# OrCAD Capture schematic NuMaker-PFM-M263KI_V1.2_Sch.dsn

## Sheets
1 Nu-Link2-Me: size A3; title: Nu-Link2-Me; rev: 1.0; company: CMHuang; note: Nu-Link2-Me
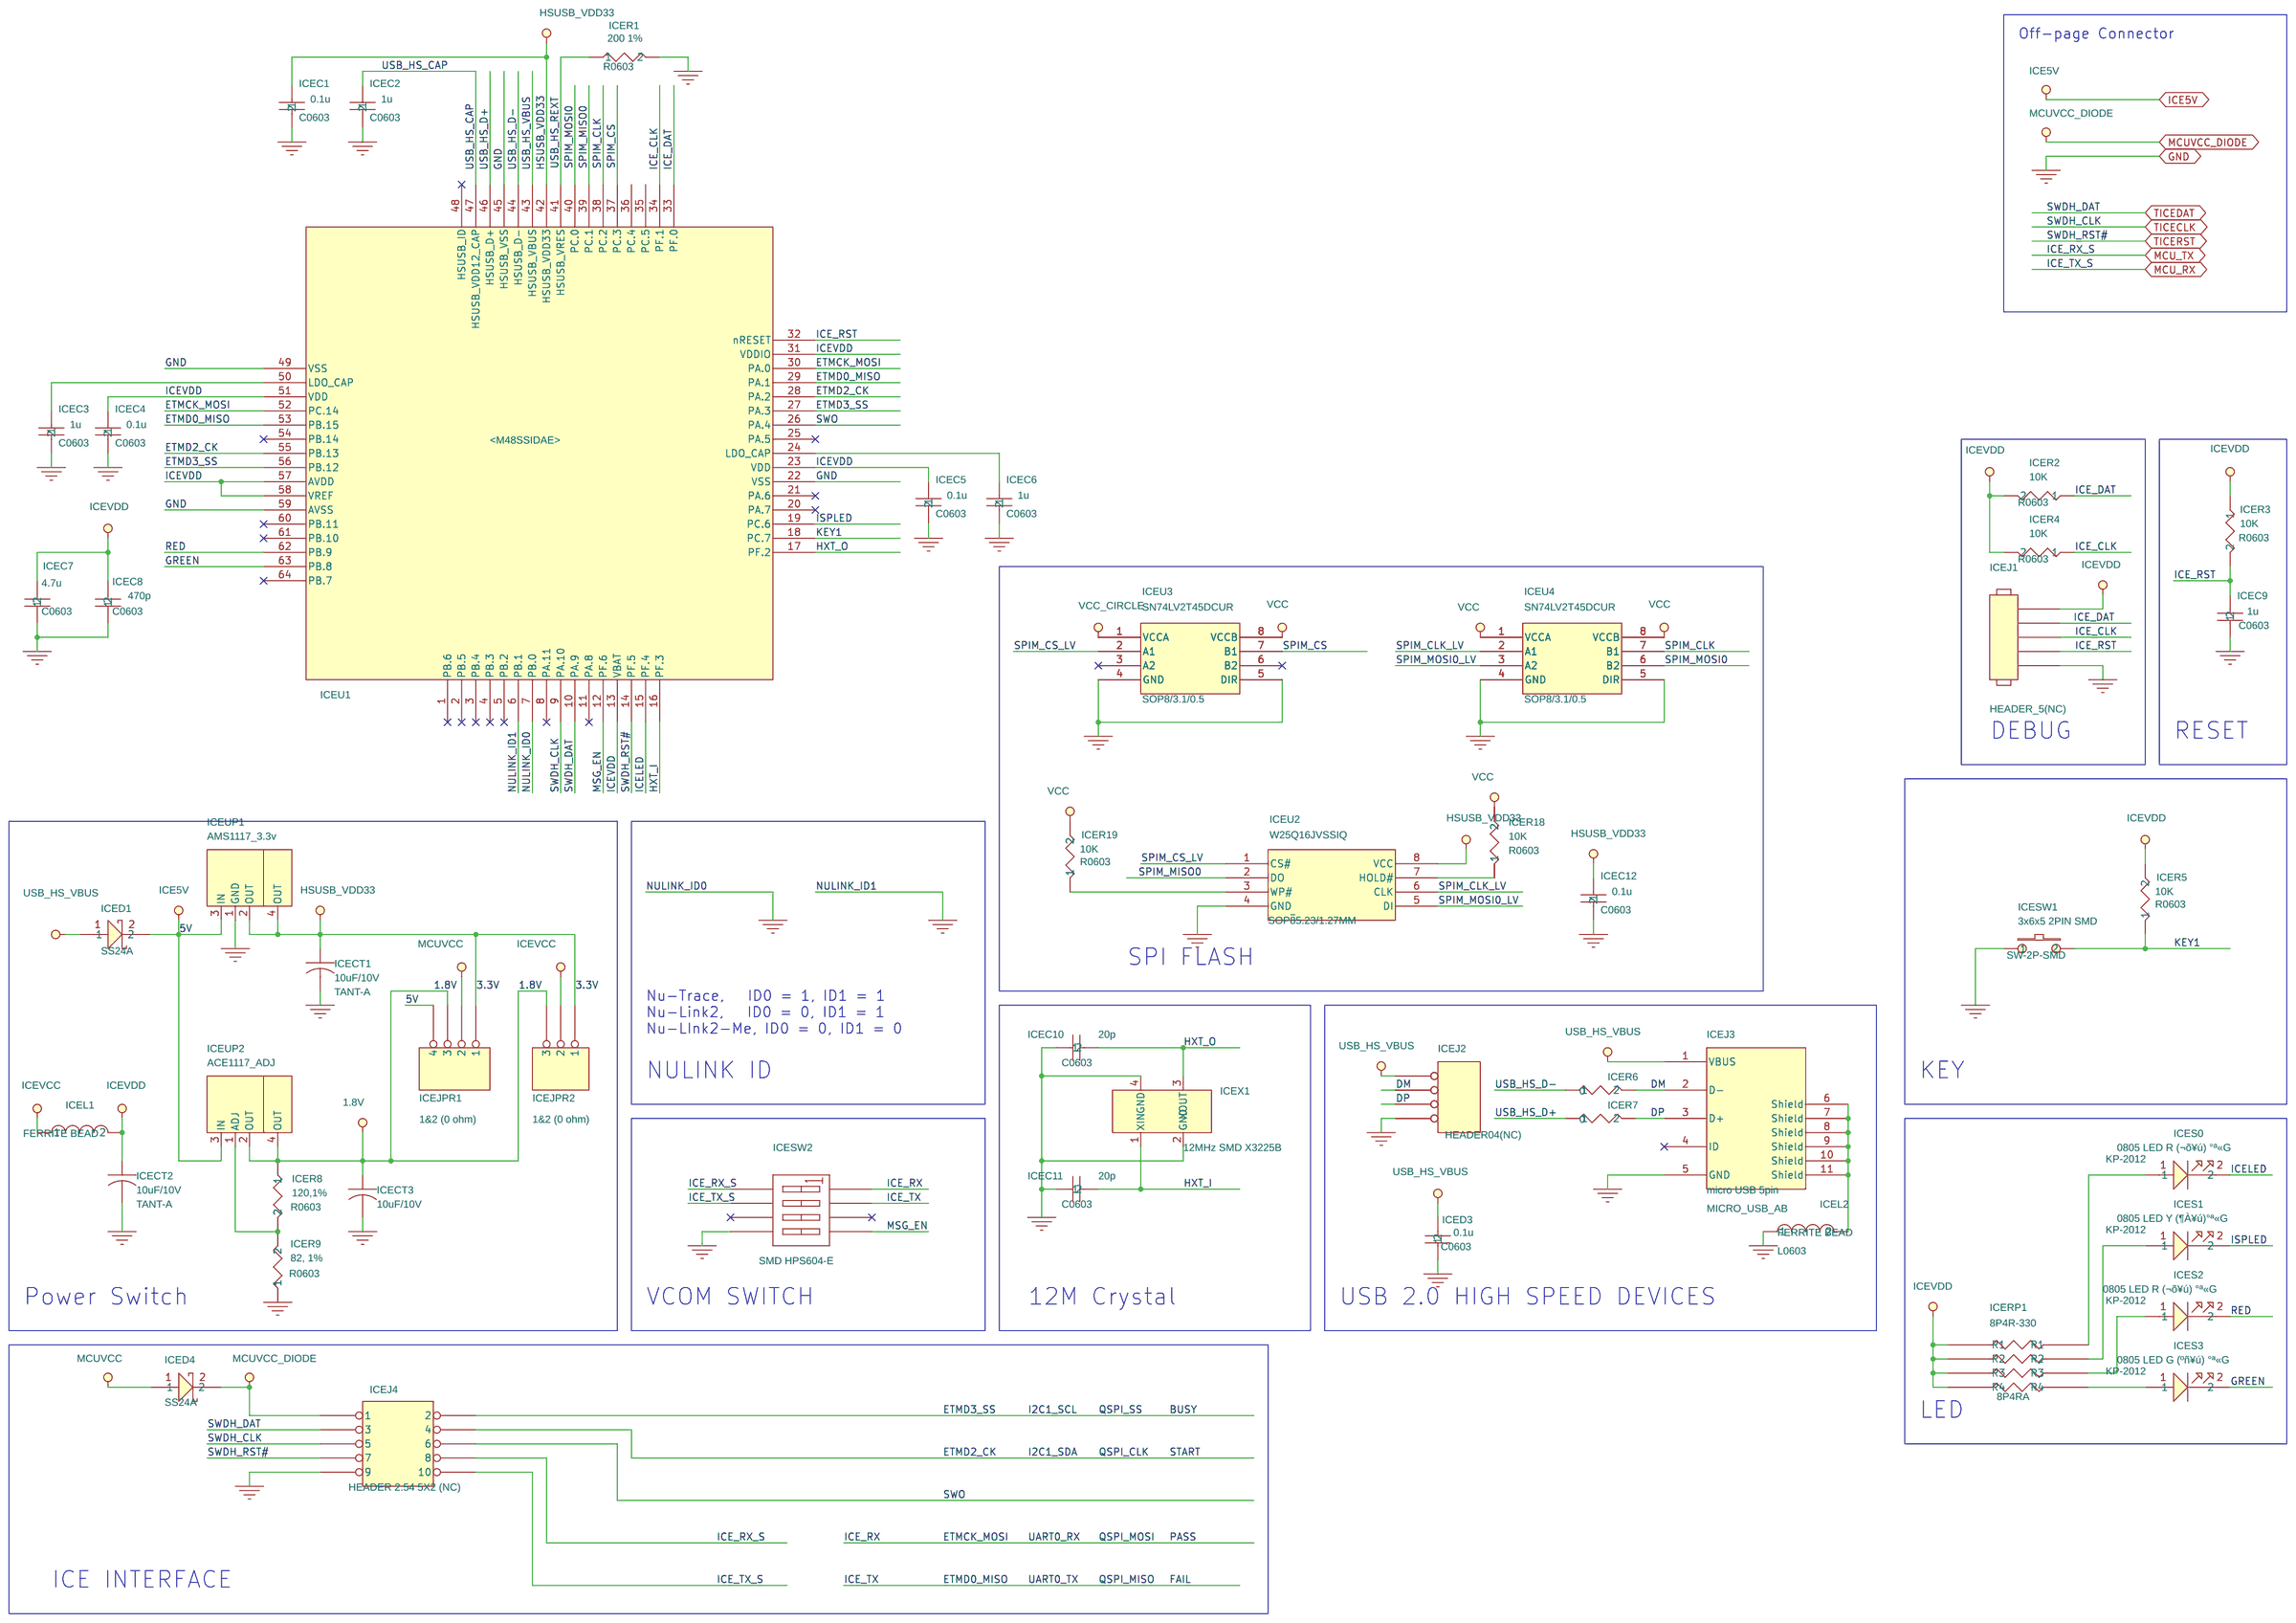
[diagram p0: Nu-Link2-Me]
2 M263KIAAE: size Custom; title: M263KIAAE; rev: v1.2; note: NuMaker-PFM-M263KI
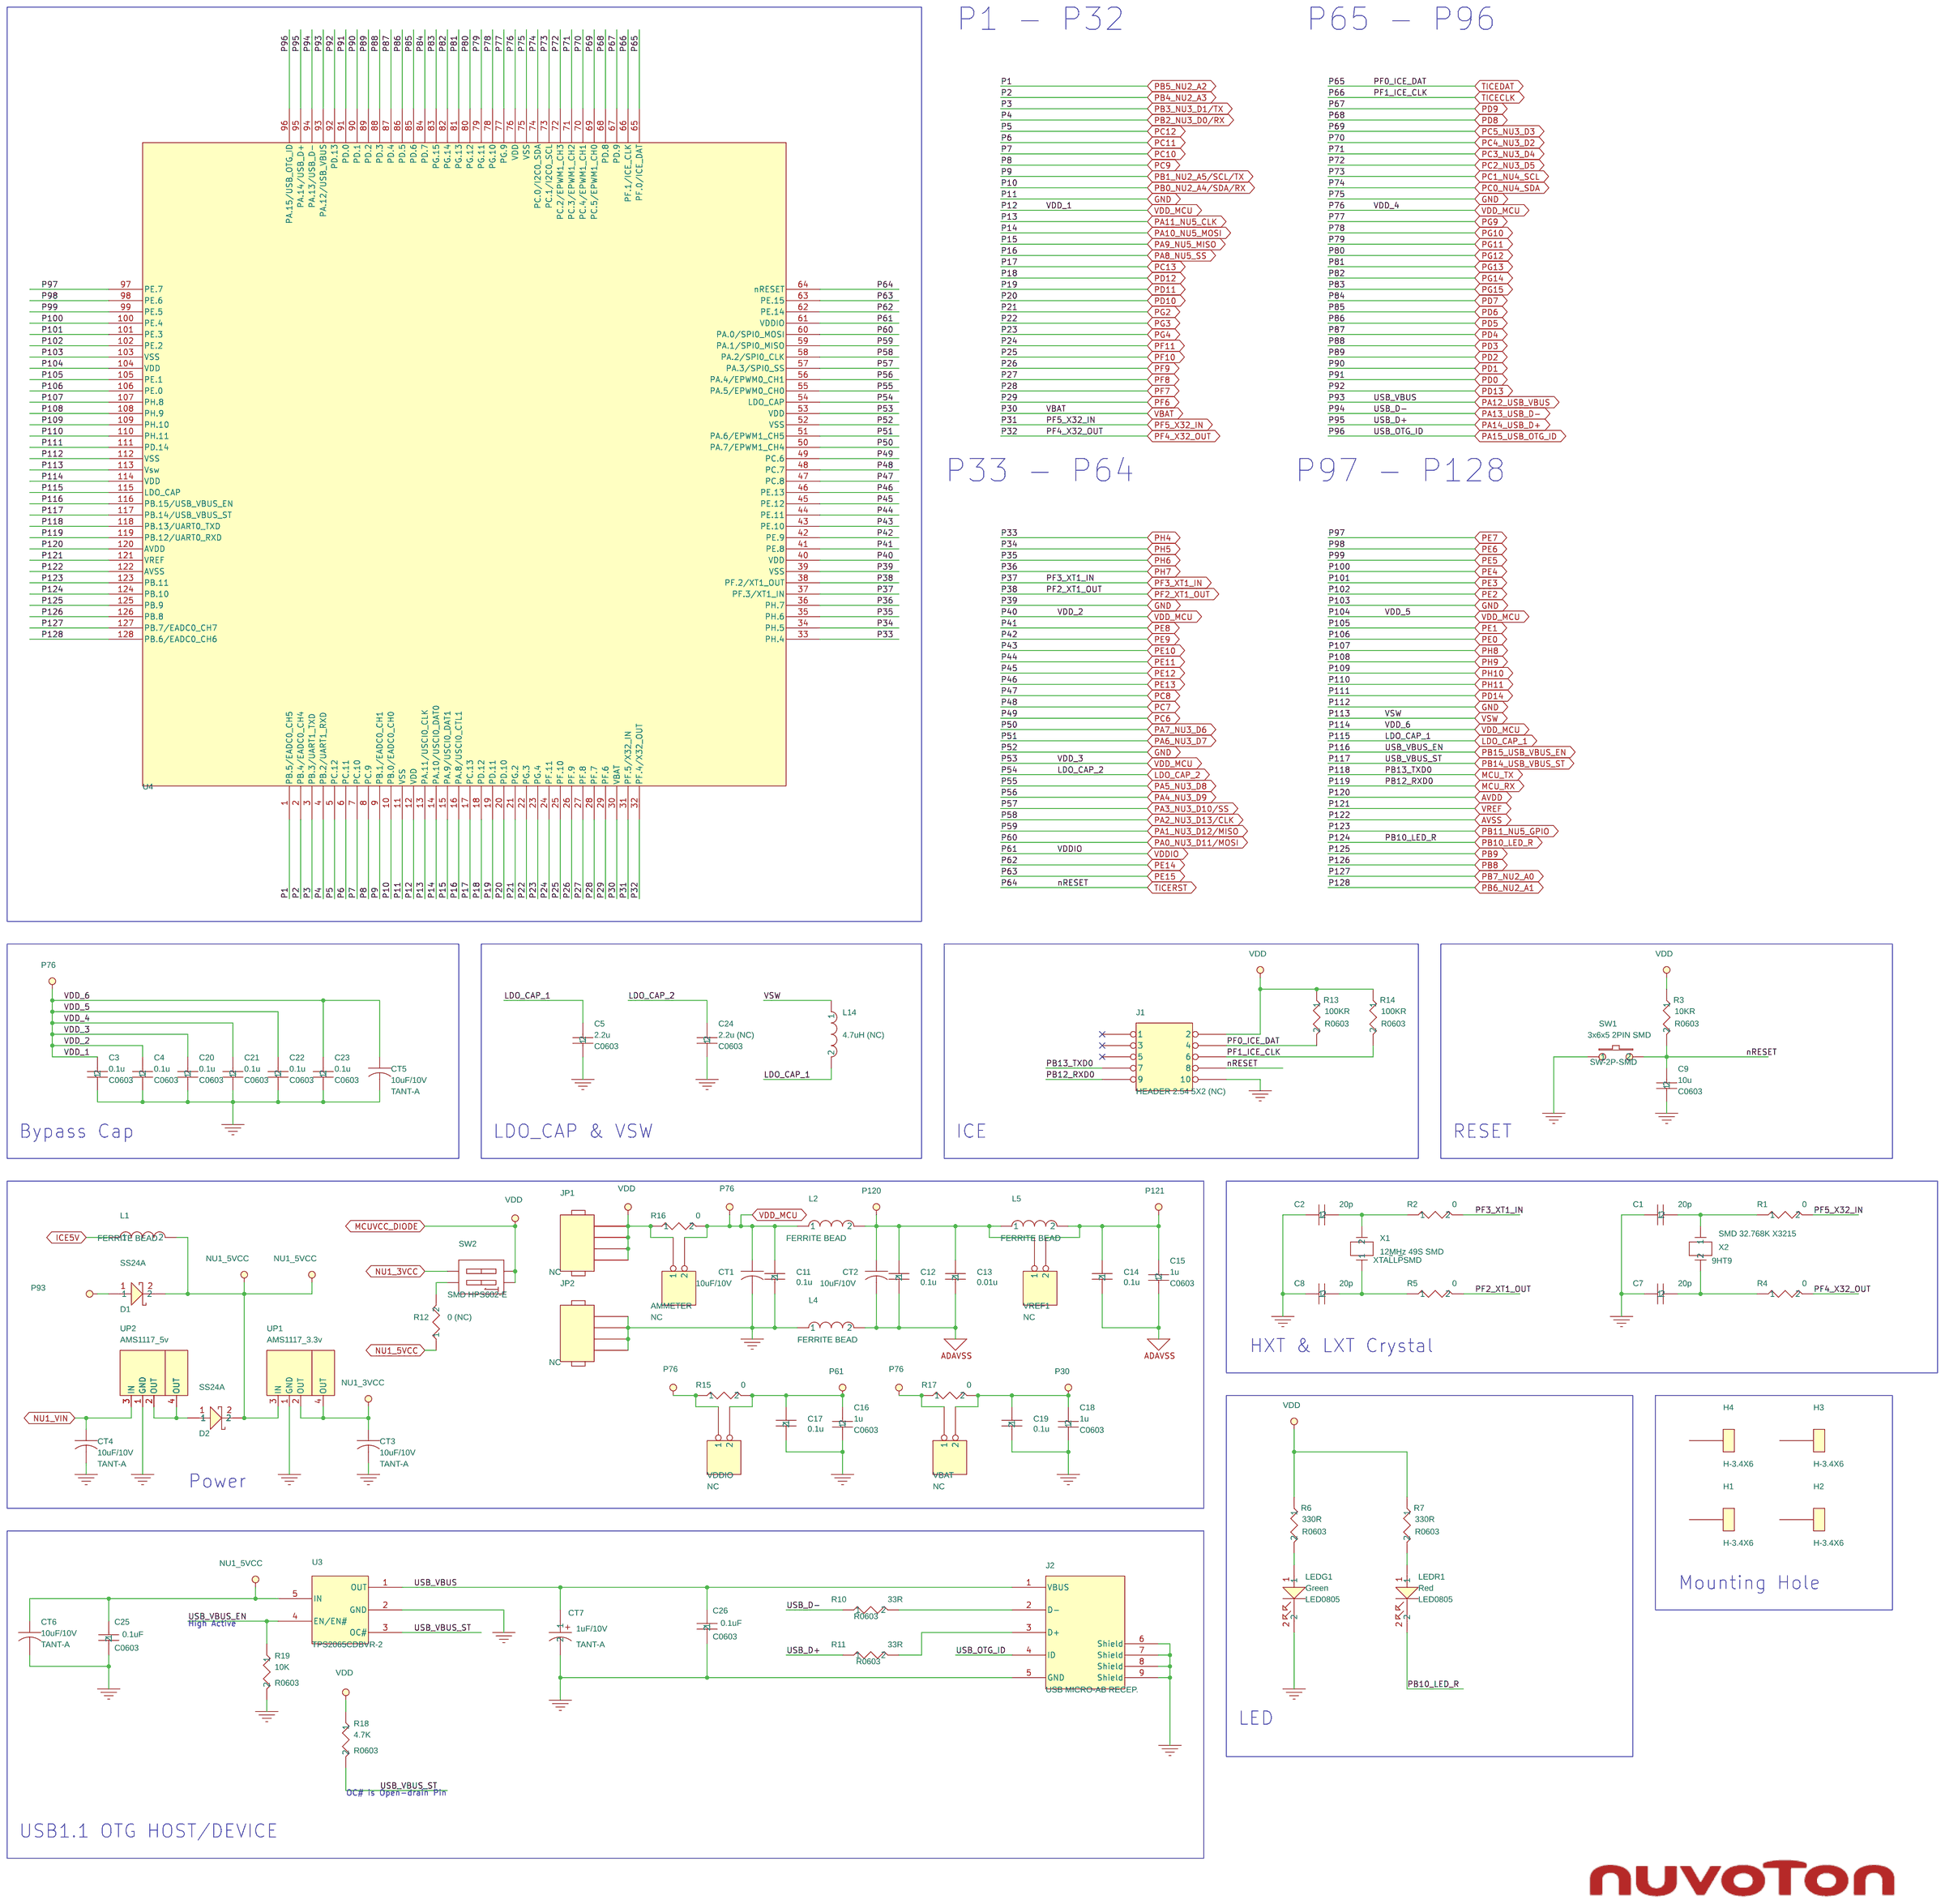
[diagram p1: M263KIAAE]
3 Ext. Connector: size Custom; title: Ext. Connector; rev: v1.2; note: NuMaker-PFM-M263KI
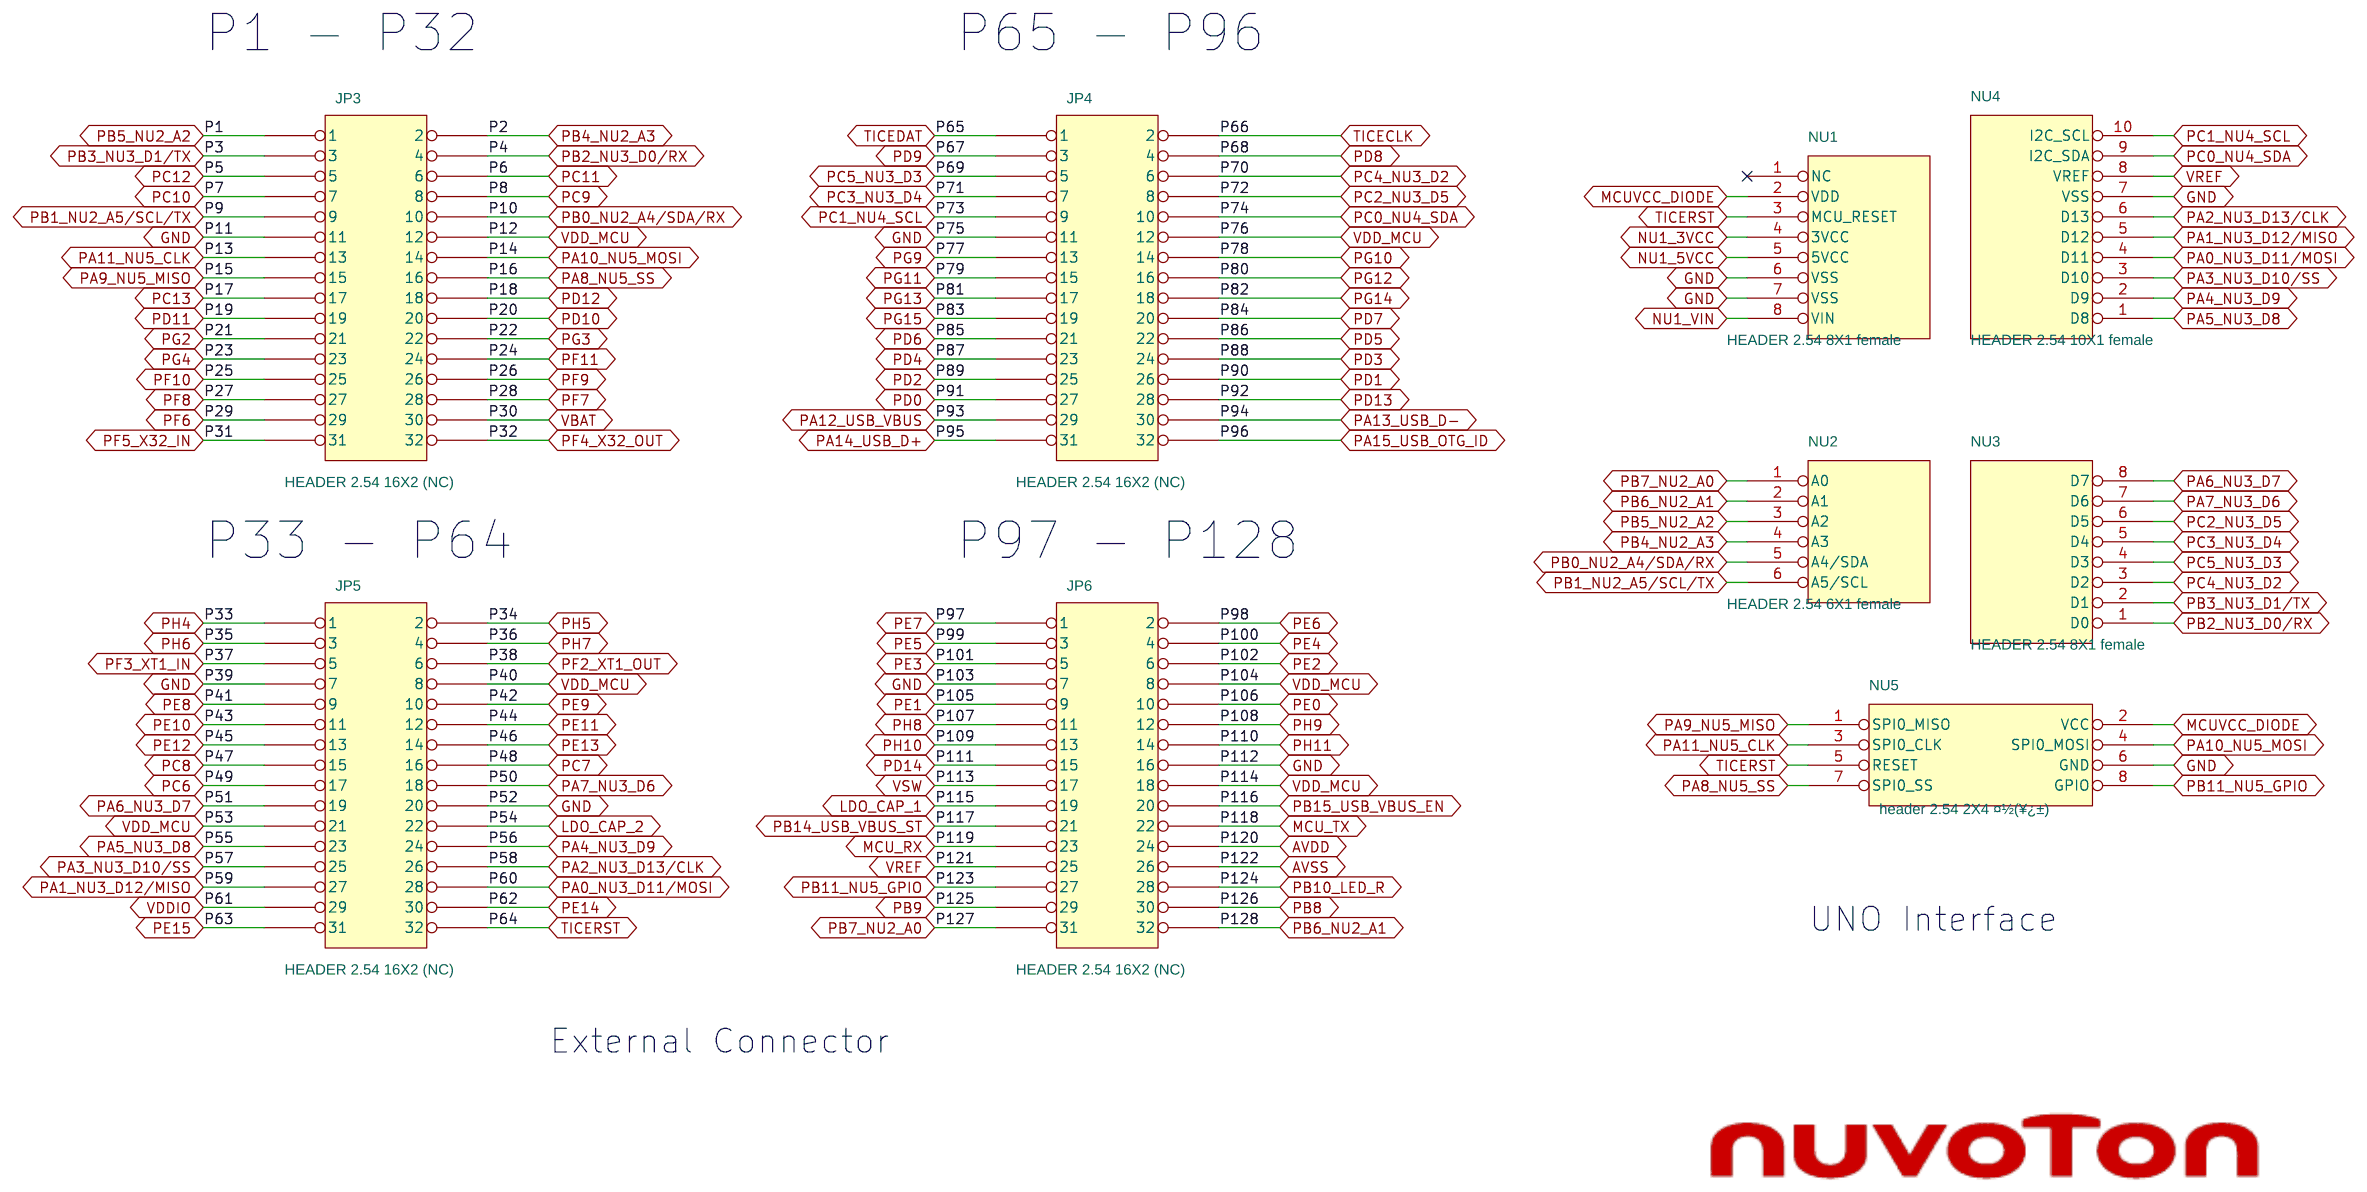
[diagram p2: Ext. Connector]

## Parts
sheet Ext. Connector
JP3  HEADER 2.54 16X2 (NC)  [HEADER16X2]
JP4  HEADER 2.54 16X2 (NC)  [HEADER16X2]
JP5  HEADER 2.54 16X2 (NC)  [HEADER16X2]
JP6  HEADER 2.54 16X2 (NC)  [HEADER16X2]
NU1  HEADER 2.54 8X1 female  [SIP-8P]
NU2  HEADER 2.54 6X1 female  [SIP-6P]
NU3  HEADER 2.54 8X1 female  [SIP-8P]
NU4  HEADER 2.54 10X1 female  [SIP-10P]
NU5  header 2.54 2X4 ¤½(¥¿­±)  [HEADER4X2]
sheet M263KIAAE
AMMETER  NC  [HEADER2X1]
C1  20p  [C0603]
C2  20p  [C0603]
C3  0.1u  [C0603]
C4  0.1u  [C0603]
C5  2.2u  [C0603]
C7  20p  [C0603]
C8  20p  [C0603]
C9  10u  [C0603]
C11  0.1u  [C0603]
C12  0.1u  [C0603]
C13  0.01u  [C0603]
C14  0.1u  [C0603]
C15  1u  [C0603]
C16  1u  [C0603]
C17  0.1u  [C0603]
C18  1u  [C0603]
C19  0.1u  [C0603]
C20  0.1u  [C0603]
C21  0.1u  [C0603]
C22  0.1u  [C0603]
C23  0.1u  [C0603]
C24  2.2u (NC)  [C0603]
C25  0.1uF  [C0603]
C26  0.1uF  [C0603]
CT1  10uF/10V  [TANT-A]
CT2  10uF/10V  [TANT-A]
CT3  10uF/10V  [TANT-A]
CT4  10uF/10V  [TANT-A]
CT5  10uF/10V  [TANT-A]
CT6  10uF/10V  [TANT-A]
CT7  1uF/10V  [TANT-A]
D1  SS24A  [RB060L]
D2  SS24A  [RB060L]
H1  H-3.4X6  [H-3.4X6]
H2  H-3.4X6  [H-3.4X6]
H3  H-3.4X6  [H-3.4X6]
H4  H-3.4X6  [H-3.4X6]
J1  HEADER 2.54 5X2 (NC)  [HEADER5X2]
J2  USB MICRO-AB RECEP.  [MICRO_USB_AB_LS]
JP1  NC  [header1x4]
JP2  NC  [header1x4]
L1  FERRITE BEAD  [L0603]
L2  FERRITE BEAD  [L0603]
L4  FERRITE BEAD  [L0603]
L5  FERRITE BEAD  [L0603]
L14  4.7uH (NC)  [L-VLF403215MT]
LEDG1  Green  [LED0805]
LEDR1  Red  [LED0805]
R1  0  [R0603]
R2  0  [R0603]
R3  10KR  [R0603]
R4  0  [R0603]
R5  0  [R0603]
R6  330R  [R0603]
R7  330R  [R0603]
R10  33R  [R0603]
R11  33R  [R0603]
R12  0 (NC)  [R0603]
R13  100KR  [R0603]
R14  100KR  [R0603]
R15  0  [R0603]
R16  0  [R0603]
R17  0  [R0603]
R18  4.7K  [R0603]
R19  10K  [R0603]
SW1  3x6x5 2PIN SMD  [SW-2P-SMD]
SW2  SMD HPS602-E  [SW1X2]
U3  TPS2065CDBVR-2  [SOT23-5]
U4  M263KIAAE  [MCU_LQFP_128_USB1_1]
UP1  AMS1117_3.3v  [SOT-223-1]
UP2  AMS1117_5v  [SOT-223-1]
VBAT  NC  [HEADER2X1]
VDDIO  NC  [HEADER2X1]
VREF1  NC  [HEADER2X1]
X1  12MHz 49S SMD  [XTAL\LP\SMD]
X2  SMD 32.768K X3215  [9HT9]
sheet Nu-Link2-Me
ICEC1  0.1u  [C0603]
ICEC2  1u  [C0603]
ICEC3  1u  [C0603]
ICEC4  0.1u  [C0603]
ICEC5  0.1u  [C0603]
ICEC6  1u  [C0603]
ICEC7  4.7u  [C0603]
ICEC8  470p  [C0603]
ICEC9  1u  [C0603]
ICEC10  20p  [C0603]
ICEC11  20p  [C0603]
ICEC12  0.1u  [C0603]
ICECT1  10uF/10V  [TANT-A]
ICECT2  10uF/10V  [TANT-A]
ICECT3  10uF/10V  [TANT-A]
ICED1  SS24A  [RB060L]
ICED3  0.1u  [C0603]
ICED4  SS24A  [RB060L]
ICEJ1  HEADER_5(NC)  [HEADER5X1]
ICEJ2  HEADER04(NC)  [HEADER04]
ICEJ3  micro USB 5pin  [MICRO_USB_AB]
ICEJ4  HEADER 2.54 5X2 (NC)  [HEADER5X2]
ICEJPR1  1&2 (0 ohm)  [R0603X3]
ICEJPR2  1&2 (0 ohm)  [R0603X2]
ICEL1  FERRITE BEAD  [L0603]
ICEL2  FERRITE BEAD  [L0603]
ICER1  200 1%  [R0603]
ICER2  10K  [R0603]
ICER3  10K  [R0603]
ICER4  10K  [R0603]
ICER5  10K  [R0603]
ICER6  0  [R0603]
ICER7  0  [R0603]
ICER8  120,1%  [R0603]
ICER9  82, 1%  [R0603]
ICER18  10K  [R0603]
ICER19  10K  [R0603]
ICERP1  8P4R-330  [8P4RA]
ICES0  0805 LED R (¬õ¥ú) °ª«G  [KP-2012]
ICES1  0805 LED Y (¶À¥ú)°ª«G  [KP-2012]
ICES2  0805 LED R (¬õ¥ú) °ª«G  [KP-2012]
ICES3  0805 LED G (ºñ¥ú) °ª«G  [KP-2012]
ICESW1  3x6x5 2PIN SMD  [SW-2P-SMD]
ICESW2  SMD HPS604-E  [SW1X4]
ICEU1  M48SSIDAE  [LQFP64_7x7_M48SSIDAE]
ICEU2  W25Q16JVSSIQ  [SOP8\5.23/1.27MM]
ICEU3  SN74LV2T45DCUR  [SOP8/3.1/0.5]
ICEU4  SN74LV2T45DCUR  [SOP8/3.1/0.5]
ICEUP1  AMS1117_3.3v  [SOT-223-1]
ICEUP2  ACE1117_ADJ  [SOT-223-1]
ICEX1  12MHz SMD X3225B  [CRYSTAL_SMD]

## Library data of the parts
JP3 = HEADER_16X2_2
JP4 = HEADER_16X2
JP5 = HEADER_16X2_3
JP6 = HEADER_16X2_1
NU1 = POWER_CONNECT_0
NU2 = ADC_CONNECT_0
NU3 = PWM0_CONNECT_0
NU4 = PWM1_CONNECT_1
NU5 = NuEdu_NU7
AMMETER = HEADER_2_2
C1 = C_20p_3
C2 = C_20p
C3 = CAP-C_2: Package: 0603; element_no: C0004
C4 = CAP-C_9: Package: 0603; element_no: C0004
C5 = CAP-C_5: Package: 0603; element_no: C0006
C7 = C_20p_1
C8 = C_20p_2
C9 ICEC3 = CAP-C_10: Package: 0603; element_no: C0006
C11 = C_0.1u_1: element_no: C0004
C12 = C_0.1u_3: element_no: C0004
C13 = C_0.1u_5: element_no: C0003
C14 = C_0.1u_2: element_no: C0004
C15 = CAP-C_6: Package: 0603; element_no: C0006
C16 ICEC2 = CAP-C_11: Package: 0603; element_no: C0006
C17 = C_0.1u_4: element_no: C0004
C18 = CAP-C_4: Package: 0603; element_no: C0006
C19 = C_0.1u: element_no: C0004
C20 = CAP-C_1: Package: 0603; element_no: C0004
C21 = CAP-C: Package: 0603; element_no: C0004
C22 ICEC1 = CAP-C_8: Package: 0603; element_no: C0004
C23 = CAP-C_3: Package: 0603; element_no: C0004
C24 = CAP-C_7: Package: 0603; element_no: C0006
C25 = CAP-B: Package: 0603
C26 = CAP-B_1: Package: 0603
CT1-CT6 ICECT1-ICECT3 = C_10uF_10V
CT7 = CAP-T: Package: TANT-R
D1 ICED4 = D_SS24A
D2 ICED1 = D_SS24A_1
H1-H4 = TEST_POINT
ICEJ4 J1 = HEADER_5X2
J2 = USB_type_B_mini_connector
JP1 JP2 = HEADER_4_v2
L1 = FERRITE_BEAD_3
L2 = FERRITE_BEAD_2
ICEL2 L4 = FERRITE_BEAD_1
ICEL1 L5 = FERRITE_BEAD
L14 = INDUCTOR
LEDG1 = LED_0_1: Package: KP-2012; Vendor: Kingbright
LEDR1 = LED_0: Package: KP-2012; Vendor: Kingbright
R1 = R_0_1
R2 = R_0_4
ICER5 R3 = R_0_5: Package: 0603
R4 = R_0_15
R5 = R_0_3
R6 = R_0_11: Package: 0603
ICER2 R7 = R_0: Package: 0603
R10 = R_0_9: Package: 0603
R11 = R_0_14: Package: 0603
R12 = R_0_10
ICER8 R13 = R_0_8: Package: 0603
R14 = R_0_12: Package: 0603
R15 = R_0_6
R16 = R_0_2
R17 = R_0_16
ICER9 R18 = R_0_7: Package: 0603
R19 = R_0_13: Package: 0603
ICESW1 SW1 = SW_PUSHBUTTON_0
SW2 = SW_DIP-4_2
U3 = NCT3520U
U4 = M263KIAAE
ICEUP1 UP1 UP2 = TO-247_Regulator_10
VBAT = HEADER_2_1
VDDIO = HEADER_2_3
VREF1 = HEADER_2
X1 = Xtal_12MHz
X2 = Xtal_32.768K
ICEC4 = CAP-C_12: Package: 0603; element_no: C0004
ICEC5 = CAP-C_5: Package: 0603; element_no: C0004
ICEC6 = CAP-C_2: Package: 0603; element_no: C0006
ICEC7 = CAP-C_3: Package: 0603
ICEC8 = CAP-C_6: Package: 0603
ICEC9 = CAP-C_9: Package: 0603; element_no: C0006
ICEC10 = CAP-C_1: Package: 0603
ICEC11 = CAP-C: Package: 0603
ICEC12 = CAP-C_4: Package: 0603; element_no: C0004
ICED3 = CAP-C_7: Package: 0603; element_no: C0004
ICEJ1 = HEADER_5
ICEJ2 = HEADER_4
ICEJ3 = micro_USB_5pin_0
ICEJPR1 = HEADER_3_0
ICEJPR2 = HEADER_3
ICER1 = R_0_6: Package: 0603
ICER3 = R_0_3: Package: 0603
ICER4 = R_0_1: Package: 0603
ICER6 = R_33_1
ICER7 = R_33
ICER18 = R_0_4: Package: 0603
ICER19 = R_0_2: Package: 0603
ICERP1 = R-PACK8_0
ICES0 = LED_0_1: Vendor: Kingbright
ICES1 = LED_0_3: Vendor: Kingbright
ICES2 = LED_0_2: Vendor: Kingbright
ICES3 = LED_0: Vendor: Kingbright
ICESW2 = SW_DIP-4_SM
ICEU1 = M487SIDAE_0: M487SIDAE: <M48SSIDAE>
ICEU2 = W25P10_20_40_SOIC_0: Package: SOP8; Vendor: WINBOND
ICEU3 ICEU4 = SN74LV2T45
ICEUP2 = TO-247_Regulator_0
ICEX1 = Crystal_SMD_1

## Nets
1.8V: ICECT3.1 ICEJPR1.3 ICEJPR2.3 ICER8.1 ICEUP2.2(OUT) ICEUP2.4(OUT)
3.3V: ICEC1.1 ICEC12.1 ICECT1.1 ICEJPR1.1 ICEJPR2.1 ICER18.2 ICER19.2 ICEU1.42(HSUSB_VDD33) ICEU2.8(VCC) ICEU3.1(VCCA) ICEU4.1(VCCA) ICEUP1.2(OUT) ICEUP1.4(OUT)
AVDD: C12.1 C13.1 CT2.1 JP6.24 L2.2 L5.1 U4.120(AVDD) VREF1.1
AVSS: C12.2 C13.2 C14.2 C15.1 CT2.2 JP6.26 L4.2 U4.122(AVSS)
GND: C1.1 C2.1 C3.1 C4.1 C5.1 C7.1 C8.1 C9.1 C11.2 C16.1 C17.2 C18.1 C19.2 C20.1 C21.1 C22.1 C23.1 C24.1 C25.2 C26.2 CT1.2 CT3.2 CT4.2 CT5.2 CT6.2 CT7.2 ICEC1.2 ICEC2.2 ICEC3.2 ICEC4.2 ICEC5.2 ICEC6.2 ICEC7.1 ICEC8.1 ICEC9.1 ICEC10.1 ICEC11.1 ICEC12.2 ICECT1.2 ICECT2.2 ICECT3.2 ICED3.1 ICEJ1.5 ICEJ2.4 ICEJ3.5(GND) ICEJ4.9 ICEL2.1 ICER1.2 ICER9.1 ICESW1.1 ICESW2.4(A4) ICEU1.6(PB.1) ICEU1.7(PB.0) ICEU1.22(VSS) ICEU1.45(HSUSB_VSS) ICEU1.49(VSS) ICEU1.59(AVSS) ICEU2.4(GND) ICEU3.4(GND) ICEU3.5(DIR) ICEU4.4(GND) ICEU4.5(DIR) ICEUP1.1(GND) ICEX1.2(GND) ICEX1.4(GND) J1.10 J2.5(GND) J2.6(Shield) J2.7(Shield) J2.8(Shield) J2.9(Shield) JP2.1 JP2.2 JP2.3 JP2.4 JP3.11 JP4.11 JP5.7 JP5.20 JP6.7 JP6.16 L4.1 LEDG1.2 NU1.6(VSS) NU1.7(VSS) NU4.7(VSS) NU5.6(GND) R19.2 SW1.1 U3.2(GND) U4.11(VSS) U4.39(VSS) U4.52(VSS) U4.75(VSS) U4.103(VSS) U4.112(VSS) UP1.1(GND) UP2.1(GND)
VBAT: C18.2 C19.1 JP3.30 R17.2 U4.30(VBAT) VBAT.2
VDD: AMMETER.1 ICED4.2 ICEJ4.1 J1.2 JP1.1 JP1.2 JP1.3 JP1.4 NU1.2(VDD) NU5.2(VCC) R3.1 R6.1 R7.1 R13.1 R14.1 R16.1 R18.1 SW2.3(B1) SW2.4(B2)
VDD_MCU: AMMETER.2 C3.2 C4.2 C11.1 C20.2 C21.2 C22.2 C23.2 CT1.1 CT5.1 JP3.12 JP4.12 JP5.8 JP5.21 JP6.8 JP6.18 L2.1 R15.1 R16.2 R17.1 U4.12(VDD) U4.40(VDD) U4.53(VDD) U4.76(VDD) U4.104(VDD) U4.114(VDD) VBAT.1 VDDIO.1
VDDIO: C16.2 C17.1 JP5.29 R15.2 U4.61(VDDIO) VDDIO.2
BUSY: ICEJ4.2 ICEU1.27(PA.3) ICEU1.56(PB.12)
DM: ICEJ2.2 ICEJ3.2(D-) ICER6.2
DP: ICEJ2.3 ICEJ3.3(D+) ICER7.2
ETMD2_CK: ICEJ4.4 ICEU1.28(PA.2) ICEU1.55(PB.13)
GREEN: ICES3.2 ICEU1.63(PB.8)
HXT_I: ICEC11.2 ICEU1.16(PF.3) ICEX1.1(XIN)
HXT_O: ICEC10.2 ICEU1.17(PF.2) ICEX1.3(XOUT)
ICE5V: ICED1.2 ICEJPR1.4 ICEUP1.3(IN) ICEUP2.3(IN) L1.1
ICE_CLK: ICEJ1.3 ICER4.1 ICEU1.34(PF.1)
ICE_DAT: ICEJ1.2 ICER2.1 ICEU1.33(PF.0)
ICE_RST: ICEC9.2 ICEJ1.4 ICER3.2 ICEU1.32(nRESET)
ICE_RX: ICESW2.8(B1) ICEU1.30(PA.0) ICEU1.52(PC.14)
ICE_TX: ICESW2.7(B2) ICEU1.29(PA.1) ICEU1.53(PB.15)
ICELED: ICES0.2 ICEU1.15(PF.4)
ICEVCC: ICEJPR2.2 ICEL1.1
ICEVDD: ICEC4.1 ICEC5.1 ICEC7.2 ICEC8.2 ICECT2.1 ICEJ1.1 ICEL1.2 ICER2.2 ICER3.1 ICER4.2 ICER5.2 ICERP1.1(R1) ICERP1.3(R2) ICERP1.5(R3) ICERP1.7(R4) ICEU1.13(VBAT) ICEU1.23(VDD) ICEU1.31(VDDIO) ICEU1.51(VDD) ICEU1.57(AVDD) ICEU1.58(VREF) ICEU3.8(VCCB) ICEU4.8(VCCB)
ISPLED: ICES1.2 ICEU1.19(PC.6)
KEY1: ICER5.1 ICESW1.2 ICEU1.18(PC.7)
LDO_CAP_1: C5.2 JP6.19 L14.2 U4.115(LDO_CAP)
LDO_CAP_2: C24.2 JP5.22 U4.54(LDO_CAP)
MCU_RX: ICEJ4.10 ICESW2.2(A2) J1.9 JP6.23 U4.119(PB.12/UART0_RXD)
MCU_TX: ICEJ4.8 ICESW2.1(A1) J1.7 JP6.22 U4.118(PB.13/UART0_TXD)
MCUVCC: ICED4.1 ICEJPR1.2
MSG_EN: ICESW2.5(B4) ICEU1.12(PF.6)
NU1_3VCC: CT3.1 NU1.4(3VCC) SW2.2(A2) UP1.2(OUT) UP1.4(OUT)
NU1_5VCC: C25.1 CT6.1 D1.2 D2.2 L1.2 NU1.5(5VCC) R12.1 U3.5(IN) UP1.3(IN)
NU1_VIN: CT4.1 NU1.8(VIN) UP2.3(IN)
PA0_NU3_D11/MOSI: JP5.28 NU4.4(D11) U4.60(PA.0/SPI0_MOSI)
PA1_NU3_D12/MISO: JP5.27 NU4.5(D12) U4.59(PA.1/SPI0_MISO)
PA2_NU3_D13/CLK: JP5.26 NU4.6(D13) U4.58(PA.2/SPI0_CLK)
PA3_NU3_D10/SS: JP5.25 NU4.3(D10) U4.57(PA.3/SPI0_SS)
PA4_NU3_D9: JP5.24 NU4.2(D9) U4.56(PA.4/EPWM0_CH1)
PA5_NU3_D8: JP5.23 NU4.1(D8) U4.55(PA.5/EPWM0_CH0)
PA6_NU3_D7: JP5.19 NU3.8(D7) U4.51(PA.6/EPWM1_CH5)
PA7_NU3_D6: JP5.18 NU3.7(D6) U4.50(PA.7/EPWM1_CH4)
PA8_NU5_SS: JP3.16 NU5.7(SPI0_SS) U4.16(PA.8/USCI0_CTL1)
PA9_NU5_MISO: JP3.15 NU5.1(SPI0_MISO) U4.15(PA.9/USCI0_DAT1)
PA10_NU5_MOSI: JP3.14 NU5.4(SPI0_MOSI) U4.14(PA.10/USCI0_DAT0)
PA11_NU5_CLK: JP3.13 NU5.3(SPI0_CLK) U4.13(PA.11/USCI0_CLK)
PA12_USB_VBUS: C26.1 CT7.1 D1.1 J2.1(VBUS) JP4.29 U3.1(OUT) U4.93(PA.12/USB_VBUS)
PA13_USB_D-: JP4.30 R10.1 U4.94(PA.13/USB_D-)
PA14_USB_D+: JP4.31 R11.1 U4.95(PA.14/USB_D+)
PA15_USB_OTG_ID: J2.4(ID) JP4.32 U4.96(PA.15/USB_OTG_ID)
PB0_NU2_A4/SDA/RX: JP3.10 NU2.5(A4/SDA) U4.10(PB.0/EADC0_CH0)
PB1_NU2_A5/SCL/TX: JP3.9 NU2.6(A5/SCL) U4.9(PB.1/EADC0_CH1)
PB2_NU3_D0/RX: JP3.4 NU3.1(D0) U4.4(PB.2/UART1_RXD)
PB3_NU3_D1/TX: JP3.3 NU3.2(D1) U4.3(PB.3/UART1_TXD)
PB4_NU2_A3: JP3.2 NU2.4(A3) U4.2(PB.4/EADC0_CH4)
PB5_NU2_A2: JP3.1 NU2.3(A2) U4.1(PB.5/EADC0_CH5)
PB6_NU2_A1: JP6.32 NU2.2(A1) U4.128(PB.6/EADC0_CH6)
PB7_NU2_A0: JP6.31 NU2.1(A0) U4.127(PB.7/EADC0_CH7)
PB8: JP6.30 U4.126(PB.8)
PB9: JP6.29 U4.125(PB.9)
PB10_LED_R: JP6.28 LEDR1.2 U4.124(PB.10)
PB11_NU5_GPIO: JP6.27 NU5.8(GPIO) U4.123(PB.11)
PB14_USB_VBUS_ST: JP6.21 R18.2 U3.3(OC#) U4.117(PB.14/USB_VBUS_ST)
PB15_USB_VBUS_EN: JP6.20 R19.1 U3.4(EN/EN#) U4.116(PB.15/USB_VBUS_EN)
PC0_NU4_SDA: JP4.10 NU4.9(I2C_SDA) U4.74(PC.0/I2C0_SDA)
PC1_NU4_SCL: JP4.9 NU4.10(I2C_SCL) U4.73(PC.1/I2C0_SCL)
PC2_NU3_D5: JP4.8 NU3.6(D5) U4.72(PC.2/EPWM1_CH3)
PC3_NU3_D4: JP4.7 NU3.5(D4) U4.71(PC.3/EPWM1_CH2)
PC4_NU3_D2: JP4.6 NU3.3(D2) U4.70(PC.4/EPWM1_CH1)
PC5_NU3_D3: JP4.5 NU3.4(D3) U4.69(PC.5/EPWM1_CH0)
PC6: JP5.17 U4.49(PC.6)
PC7: JP5.16 U4.48(PC.7)
PC8: JP5.15 U4.47(PC.8)
PC9: JP3.8 U4.8(PC.9)
PC10: JP3.7 U4.7(PC.10)
PC11: JP3.6 U4.6(PC.11)
PC12: JP3.5 U4.5(PC.12)
PC13: JP3.17 U4.17(PC.13)
PD0: JP4.27 U4.91(PD.0)
PD1: JP4.26 U4.90(PD.1)
PD2: JP4.25 U4.89(PD.2)
PD3: JP4.24 U4.88(PD.3)
PD4: JP4.23 U4.87(PD.4)
PD5: JP4.22 U4.86(PD.5)
PD6: JP4.21 U4.85(PD.6)
PD7: JP4.20 U4.84(PD.7)
PD8: JP4.4 U4.68(PD.8)
PD9: JP4.3 U4.67(PD.9)
PD10: JP3.20 U4.20(PD.10)
PD11: JP3.19 U4.19(PD.11)
PD12: JP3.18 U4.18(PD.12)
PD13: JP4.28 U4.92(PD.13)
PD14: JP6.15 U4.111(PD.14)
PE0: JP6.10 U4.106(PE.0)
PE1: JP6.9 U4.105(PE.1)
PE2: JP6.6 U4.102(PE.2)
PE3: JP6.5 U4.101(PE.3)
PE4: JP6.4 U4.100(PE.4)
PE5: JP6.3 U4.99(PE.5)
PE6: JP6.2 U4.98(PE.6)
PE7: JP6.1 U4.97(PE.7)
PE8: JP5.9 U4.41(PE.8)
PE9: JP5.10 U4.42(PE.9)
PE10: JP5.11 U4.43(PE.10)
PE11: JP5.12 U4.44(PE.11)
PE12: JP5.13 U4.45(PE.12)
PE13: JP5.14 U4.46(PE.13)
PE14: JP5.30 U4.62(PE.14)
PE15: JP5.31 U4.63(PE.15)
PF2_XT1_OUT: JP5.6 R5.2 U4.38(PF.2/XT1_OUT)
PF3_XT1_IN: JP5.5 R2.2 U4.37(PF.3/XT1_IN)
PF4_X32_OUT: JP3.32 R4.2 U4.32(PF.4/X32_OUT)
PF5_X32_IN: JP3.31 R1.2 U4.31(PF.5/X32_IN)
PF6: JP3.29 U4.29(PF.6)
PF7: JP3.28 U4.28(PF.7)
PF8: JP3.27 U4.27(PF.8)
PF9: JP3.26 U4.26(PF.9)
PF10: JP3.25 U4.25(PF.10)
PF11: JP3.24 U4.24(PF.11)
PG2: JP3.21 U4.21(PG.2)
PG3: JP3.22 U4.22(PG.3)
PG4: JP3.23 U4.23(PG.4)
PG9: JP4.13 U4.77(PG.9)
PG10: JP4.14 U4.78(PG.10)
PG11: JP4.15 U4.79(PG.11)
PG12: JP4.16 U4.80(PG.12)
PG13: JP4.17 U4.81(PG.13)
PG14: JP4.18 U4.82(PG.14)
PG15: JP4.19 U4.83(PG.15)
PH4: JP5.1 U4.33(PH.4)
PH5: JP5.2 U4.34(PH.5)
PH6: JP5.3 U4.35(PH.6)
PH7: JP5.4 U4.36(PH.7)
PH8: JP6.11 U4.107(PH.8)
PH9: JP6.12 U4.108(PH.9)
PH10: JP6.13 U4.109(PH.10)
PH11: JP6.14 U4.110(PH.11)
RED: ICES2.2 ICEU1.62(PB.9)
SPIM_CLK: ICEU1.38(PC.2) ICEU4.7(B1)
SPIM_CLK_LV: ICEU2.6(CLK) ICEU4.2(A1)
SPIM_CS: ICEU1.37(PC.3) ICEU3.7(B1)
SPIM_CS_LV: ICEU2.1(CS#) ICEU3.2(A1)
SPIM_MISO0: ICEU1.39(PC.1) ICEU2.2(DO)
SPIM_MOSI0: ICEU1.40(PC.0) ICEU4.6(B2)
SPIM_MOSI0_LV: ICEU2.5(DI) ICEU4.3(A2)
SWO: ICEJ4.6 ICEU1.26(PA.4)
TICECLK: ICEJ4.5 ICEU1.9(PA.10) J1.6 JP4.2 R14.2 U4.66(PF.1/ICE_CLK)
TICEDAT: ICEJ4.3 ICEU1.10(PA.9) J1.4 JP4.1 R13.2 U4.65(PF.0/ICE_DAT)
TICERST: C9.2 ICEJ4.7 ICEU1.14(PF.5) J1.8 JP5.32 NU1.3(MCU_RESET) NU5.5(RESET) R3.2 SW1.2 U4.64(nRESET)
USB_HS_CAP: ICEC2.1 ICEU1.47(HSUSB_VDD12_CAP)
USB_HS_D+: ICER7.1 ICEU1.46(HSUSB_D+)
USB_HS_D-: ICER6.1 ICEU1.44(HSUSB_D-)
USB_HS_REXT: ICER1.1 ICEU1.41(HSUSB_VRES)
USB_HS_VBUS: ICED1.1 ICED3.2 ICEJ2.1 ICEJ3.1(VBUS) ICEU1.43(HSUSB_VBUS)
VREF: C14.1 C15.2 JP6.25 L5.2 NU4.8(VREF) U4.121(VREF) VREF1.2
VSW: JP6.17 L14.1 U4.113(Vsw)
N16825237: LEDG1.1 R6.2
N16825240: LEDR1.1 R7.2
N16840819: ICEC6.1 ICEU1.24(LDO_CAP)
N16840960: ICEC3.1 ICEU1.50(LDO_CAP)
N17019924: ICER8.2 ICER9.2 ICEUP2.1(ADJ)
N17029977: ICERP1.8(R4) ICES3.1
N17029979: ICERP1.6(R3) ICES2.1
N17030004: ICERP1.4(R2) ICES1.1
N17030010: ICERP1.2(R1) ICES0.1
N17042369: ICEJ3.6(Shield) ICEJ3.7(Shield) ICEJ3.8(Shield) ICEJ3.9(Shield) ICEJ3.10(Shield) ICEJ3.11(Shield) ICEL2.2
N17125028: R12.2 SW2.1(A1)
N17155328: ICER18.1 ICEU2.7(HOLD#)
N17155343: ICER19.1 ICEU2.3(WP#)
N17159369: C8.2 R5.1 X1.1
N17159371: C2.2 R2.1 X1.2
N17159463: C1.2 R1.1 X2.1
N17159465: C7.2 R4.1 X2.2
N17167442: D2.1 UP2.2(OUT) UP2.4(OUT)
N17266794: J2.3(D+) R11.2
N17266796: J2.2(D-) R10.2

Not connected (* = marked no-connect by the designer): H1 1; H2 1; H3 1; H4 1; ICEJ3 4(ID)*; ICESW2 3(A3)* 6(B3)*; ICEU1 1(PB.6)* 2(PB.5)* 3(PB.4)* 4(PB.3)* 5(PB.2)* 8(PA.11)* 11(PA.8)* 20(PA.7)* 21(PA.6)* 25(PA.5)* 35(PC.5) 36(PC.4) 48(HSUSB_ID)* 54(PB.14)* 60(PB.11)* 61(PB.10)* 64(PB.7)*; ICEU3 3(A2)* 6(B2)*; J1 1* 3* 5*; NU1 1(NC)*

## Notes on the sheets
sheet 1
- Off-page Connector
- DEBUG
- RESET
- SPI FLASH
- Nu-Trace,   ID0 = 1, ID1 = 1
  Nu-Link2,   ID0 = 0, ID1 = 1
  Nu-LInk2-Me, ID0 = 0, ID1 = 0
- NULINK ID
- KEY
- Power Switch
- VCOM SWITCH
- 12M Crystal
- USB 2.0 HIGH SPEED DEVICES
- LED
- ICE INTERFACE
sheet 2
- P1 - P32
- P65 - P96
- P33 - P64
- P97 - P128
- Bypass Cap
- LDO_CAP & VSW
- ICE
- RESET
- HXT & LXT Crystal
- Power
- Mounting Hole
- High Active
- LED
- OC# is Open-drain Pin
- USB1.1 OTG HOST/DEVICE
sheet 3
- P1 - P32
- P65 - P96
- P33 - P64
- P97 - P128
- UNO Interface
- External Connector
